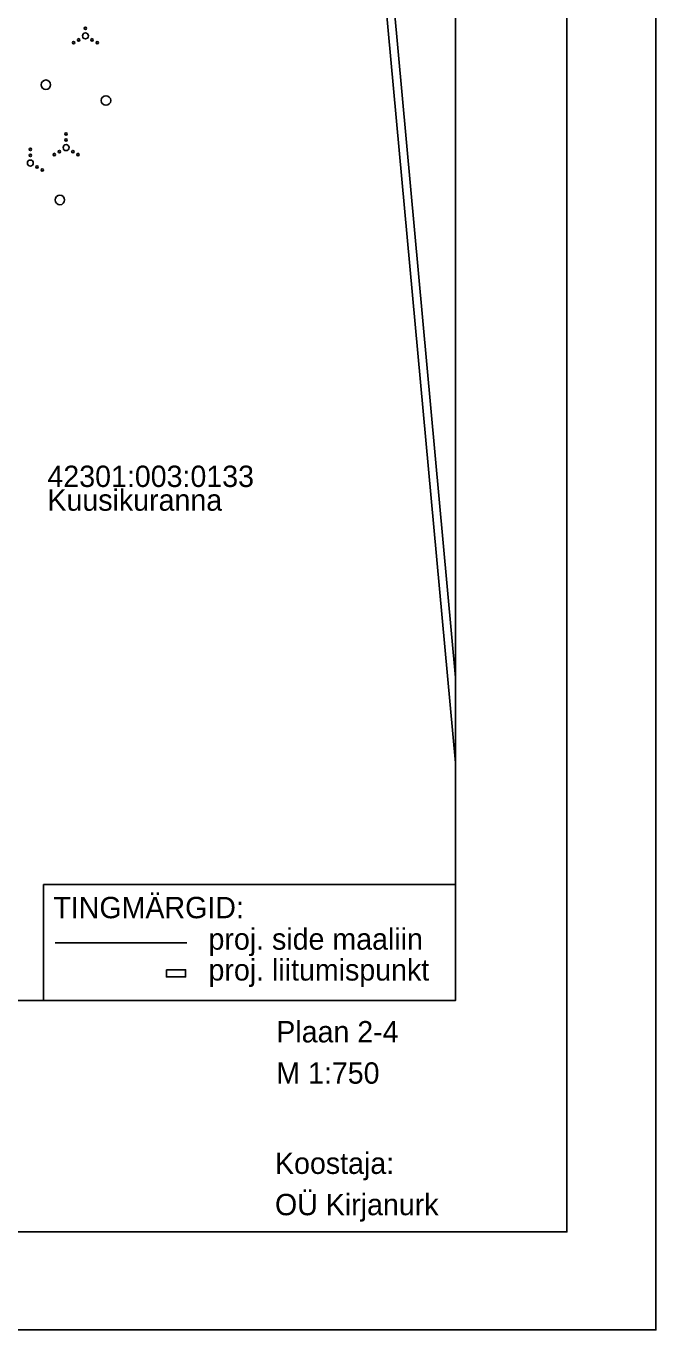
# Model space of a CAD drawing. Extents: x 599446 to 599962, y 6608194 to 6608886.
# Drawn here: x 599909.2 to 599962.3, y 6608663.4 to 6608773.2 of the extents above; entities that cross this region are included whole.
import ezdxf

# ---------------------------------------------------------------- set-up
doc = ezdxf.new("R2010")
doc.units = 0
for name, color, linetype in [('HALJASTUS', 7, 'Continuous'), ('PIIR', 7, 'Continuous'), ('VORMISTUS_3', 7, 'Continuous')]:
    doc.layers.add(name, color=color, linetype=linetype)

msp = doc.modelspace()

# ---------------------------------------------------------------- linework, layer by layer
at = {"layer": 'HALJASTUS'}
for centre, radius in [((599914.21, 6608772.37), 0.25), ((599914.21, 6608773.02), 0.1), ((599913.21, 6608771.79), 0.1), ((599913.64, 6608772.04), 0.1), ((599914.77, 6608772.04), 0.1), ((599915.21, 6608771.79), 0.1), ((599910.88, 6608768.26), 0.4), ((599915.94, 6608766.93), 0.4), ((599912.58, 6608764.11), 0.1), ((599912.58, 6608763.61), 0.1), ((599909.57, 6608762.81), 0.1), ((599909.57, 6608762.31), 0.1), ((599911.58, 6608762.38), 0.1), ((599912.02, 6608762.63), 0.1), ((599912.58, 6608762.96), 0.25), ((599913.15, 6608762.63), 0.1), ((599913.58, 6608762.38), 0.1), ((599909.57, 6608761.66), 0.25), ((599910.13, 6608761.33), 0.1), ((599910.57, 6608761.08), 0.1), ((599912.06, 6608758.55), 0.4)]:
    msp.add_circle(centre, radius, dxfattribs=at)
at = {"layer": 'PIIR'}
for points in [[(599945.4, 6608711.12), (599935.43, 6608819.59), (599932.44, 6608820.83), (599945.4, 6608848.39)], [(599894.31, 6608691.11), (599886.06, 6608744.32), (599936.05, 6608820.15), (599945.4, 6608718.31)]]:
    msp.add_lwpolyline(points, dxfattribs=at)
at = {"layer": 'VORMISTUS_3'}
msp.add_line((599922.75, 6608695.96), (599911.67, 6608695.96), dxfattribs=at)
for points in [[(599804.77, 6608886.11), (599962.27, 6608886.11), (599962.27, 6608663.36), (599804.77, 6608663.36)], [(599812.27, 6608671.61), (599954.77, 6608671.61), (599954.77, 6608877.86), (599812.27, 6608877.86)], [(599812.27, 6608877.86), (599954.77, 6608877.86), (599954.77, 6608671.61), (599812.27, 6608671.61)], [(599945.4, 6608691.11), (599821.65, 6608691.11), (599821.65, 6608848.61), (599945.4, 6608848.61)], [(599910.67, 6608700.88), (599945.4, 6608700.88), (599945.4, 6608691.11), (599910.67, 6608691.11)], [(599921.03, 6608693.7), (599922.65, 6608693.7), (599922.65, 6608693.1), (599921.03, 6608693.1)]]:
    msp.add_lwpolyline(points, close=True, dxfattribs=at)

# ---------------------------------------------------------------- texts
at = {"layer": 'PIIR'}
for s, p in [('42301:003:0133', (599911.01, 6608734.37)), ('Kuusikuranna', (599911.01, 6608732.37))]:
    msp.add_text(s, height=1.8, dxfattribs=at).set_placement(p)
at = {"layer": 'VORMISTUS_3'}
for s, p in [('TINGMÄRGID:', (599911.51, 6608698.04)), ('proj. side maaliin', (599924.58, 6608695.39)), ('proj. liitumispunkt', (599924.58, 6608692.79)), ('Plaan 2-4', (599930.29, 6608687.58)), ('M 1:750', (599930.29, 6608684.1)), ('Koostaja:', (599930.18, 6608676.5)), ('OÜ Kirjanurk', (599930.18, 6608673.02))]:
    msp.add_text(s, height=1.8, dxfattribs=at).set_placement(p)

doc.saveas('drawing.dxf')
